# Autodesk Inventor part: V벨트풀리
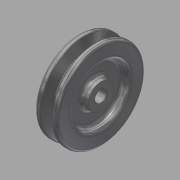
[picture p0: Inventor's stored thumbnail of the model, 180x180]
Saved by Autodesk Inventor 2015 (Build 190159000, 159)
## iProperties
Created: 2015-11
Part Number: V벨트풀리
Material: 강철, 탄소
Document SubType Name: Modeling
Designer: mduedu
Density: 1 g/cm^3
Appearance: 반광택
Author: mduedu
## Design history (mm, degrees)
sketch "스케치1"
  geometry: L1 (-9.5, 0)-(9.5, 0); L2 (0, 0)-(0, 37.7); L3 (-4.825, 37.7)-(-9.5, 37.7); L4 (-9.5, 37.7)-(-9.5, 0); L5 (0, 28.7)-(-2.074, 28.7); L6 (-2.074, 28.7)-(-4.825, 37.7); L7 (4.825, 37.7)-(9.5, 37.7); L8 (9.5, 37.7)-(9.5, 0); L9 (0, 28.7)-(2.074, 28.7); L10 (2.074, 28.7)-(4.825, 37.7); L11 (-9.5, 35)-(9.5, 35); 3 further points
  constraints: 22 end point, 7 point on line, 4 perpendicular, 3 symmetric about line, 1 coincident, 1 horizontal, 1 horizontal alignment, 1 midpoint, 1 vertical
  dimensions: "d0" = 19 distance of L1.start L1.end; "d2" = 75.4 diameter of L2.end L1 (derived); "d3" = 34 deg angle of L10 L6; "d4" = 6.3 distance between parallel lines of L11 L9; "d5" = 2.7 distance between parallel lines of L7 L11; "d6" = 8 distance of point (4, 35) point (-4, 35); "d7" = 70 diameter of L11 L1
revolve "회전1" sketch "스케치1" stored, may be unused: angle "d8" = 90 deg
sketch "스케치2"
  geometry: C1 r 24 at (0, 0); C2 r 11 at (0, 0); 1 further point
  constraints: 2 centre point, 2 coincident
  dimensions: "d9" = 48 diameter of C1; "d10" = 22 diameter of C2
extrude "돌출1" cut sketch "스케치2" distance "d11" = 6; taper "d12" = 0 deg
fillet "모깎기1" dims "d13" = 3
fillet "모깎기2" dims "d14" = 3
fillet "모깎기3" dims "d15" = 1, "d16" = 0.5, "d17" = 2
hole "구멍1" diameter "d20" = 10; stored, may be unused: countersink angle "d24" = 90 deg, drill point angle "d26" = 118 deg; dims "d18" = 10, "d19" = 10, "d21" = 6, "d22" = 4, "d23" = 2, "d25" = 8
sketch "스케치3"
  geometry: L1 (-1.5, 0)-(1.5, 0); L2 (1.5, 0)-(1.5, 6.4); L3 (1.5, 6.4)-(-1.5, 6.4); L4 (-1.5, 6.4)-(-1.5, 0); 2 further points
  constraints: 8 end point, 2 parallel, 1 coincident, 1 horizontal, 1 midpoint, 1 perpendicular
  dimensions: "d27" = 3 distance of L2.end L3.end; "d29" = 6.4 distance of L3.end L1.start
extrude "돌출2" cut sketch "스케치3" stored distance "d30" = 6; taper "d31" = 0 deg
chamfer "모따기1" distance "d32" = 0.5; stored, may be unused: second distance "d33" = 2, angle "d34" = 45 deg
node "솔리드1"
mirror "대칭1"
